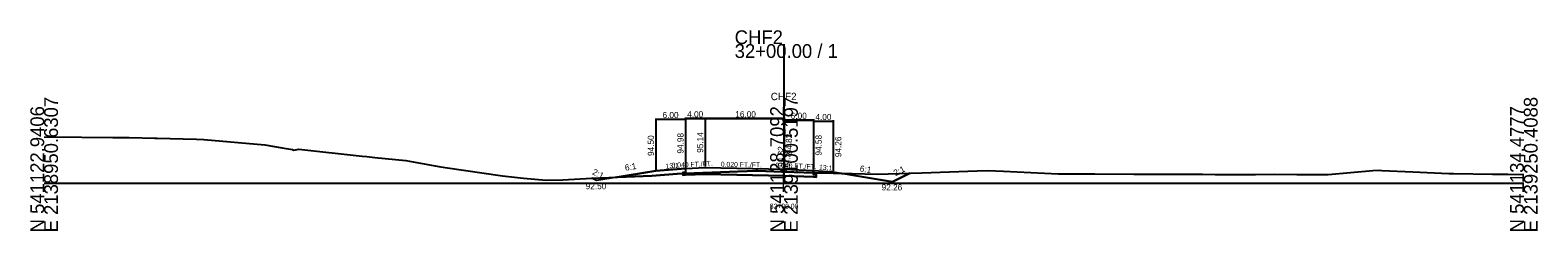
# Model space of a CAD drawing. Extents: x -12831 to 2303, y -10 to 39065.
# Drawn here: x 997.2 to 1302.8, y 3990.3 to 4031 of the extents above; entities that cross this region are included whole.
import ezdxf

# ---------------------------------------------------------------- set-up
doc = ezdxf.new("R2010")
doc.units = 0
for name, color, linetype in [('Level 5', 7, 'Continuous'), ('Level 53', 7, 'Continuous'), ('Level 54', 7, 'Continuous'), ('Level 55', 7, 'Continuous'), ('Level 7', 7, 'Continuous'), ('RD_GPK_XS_Cell', 7, 'Continuous'), ('RD_XS_EwShp', 7, 'Continuous'), ('RD_XS_ExGround', 7, 'Continuous'), ('RD_XS_Pave', 7, 'Continuous'), ('RD_XS_TX_Baseline', 7, 'Continuous'), ('RD_XS_TX_Ditch', 7, 'Continuous'), ('RD_XS_TX_Elev_EX', 7, 'Continuous'), ('RD_XS_TX_Elev_PR', 7, 'Continuous'), ('RD_XS_TX_Station', 7, 'Continuous')]:
    doc.layers.add(name, color=color, linetype=linetype)

msp = doc.modelspace()

# ---------------------------------------------------------------- linework, layer by layer
at = {"layer": 'Level 5'}
for p, q in [((1130, 4002.15), (1129.5, 4002.13)), ((1129.5, 4002.13), (1129.5, 4001.63)), ((1129.5, 4001.63), (1130, 4001.65)), ((1130, 4002.98), (1130, 4002.15)), ((1134, 4001.81), (1130, 4001.65)), ((1134, 4001.81), (1130, 4001.65)), ((1130, 4001.65), (1134, 4001.81)), ((1150, 4001.49), (1134, 4001.81)), ((1150, 4001.49), (1134, 4001.81)), ((1134, 4001.81), (1150, 4001.49)), ((1134, 4001.81), (1150, 4001.49)), ((1156, 4001.25), (1150, 4001.49)), ((1150, 4001.49), (1156, 4001.25)), ((1150, 4001.49), (1156, 4001.25)), ((1156, 4002.58), (1156, 4001.75)), ((1156, 4001.75), (1156.5, 4001.73)), ((1156.5, 4001.73), (1156.5, 4001.23)), ((1156.5, 4001.23), (1156, 4001.25))]:
    msp.add_line(p, q, dxfattribs=at)
at = {"layer": 'Level 54'}
for p, q in [((1124, 4013.13), (1124, 4002.7)), ((1130, 4012.93), (1124, 4012.93)), ((1130, 4013.29), (1130, 4003.18)), ((1130, 4013.29), (1130, 4003.18)), ((1130, 4013.29), (1130, 4003.18)), ((1130, 4013.13), (1130, 4003.18)), ((1130, 4013.09), (1134, 4013.09)), ((1130, 4013.09), (1134, 4013.09)), ((1134, 4013.09), (1130, 4013.09)), ((1134, 4013.29), (1134, 4003.34)), ((1134, 4013.29), (1134, 4003.34)), ((1134, 4013.29), (1134, 4003.34)), ((1134, 4013.29), (1134, 4003.34)), ((1134, 4013.29), (1134, 4003.34)), ((1134, 4013.29), (1134, 4003.34)), ((1134, 4013.29), (1134, 4003.34)), ((1134, 4013.09), (1150, 4013.09)), ((1134, 4013.09), (1150, 4013.09)), ((1150, 4013.09), (1134, 4013.09)), ((1150, 4013.09), (1134, 4013.09)), ((1150, 4013.29), (1150, 4003.02)), ((1150, 4013.29), (1150, 4003.02)), ((1150, 4013.29), (1150, 4003.02)), ((1150, 4013.29), (1150, 4003.02)), ((1150, 4012.97), (1150, 4003.02)), ((1150, 4012.97), (1150, 4003.02)), ((1150, 4012.97), (1150, 4003.02)), ((1150, 4012.77), (1156, 4012.77)), ((1156, 4012.77), (1150, 4012.77)), ((1156, 4012.77), (1150, 4012.77)), ((1156, 4012.97), (1156, 4002.78)), ((1156, 4012.97), (1156, 4002.78)), ((1156, 4012.97), (1156, 4002.78)), ((1156, 4012.73), (1156, 4002.78)), ((1156, 4012.53), (1160, 4012.53)), ((1160, 4012.73), (1160, 4002.46))]:
    msp.add_line(p, q, dxfattribs=at)
at = {"layer": 'Level 7'}
for p, q in [((1124, 4002.5), (1112, 4000.5)), ((1130, 4002.98), (1124, 4002.5)), ((1156, 4002.58), (1160, 4002.26)), ((1160, 4002.26), (1172, 4000.26)), ((1172, 4000.26), (1175.53, 4002.02)), ((1112, 4000.5), (1111.02, 4000.99))]:
    msp.add_line(p, q, dxfattribs=at)
at = {"layer": 'RD_GPK_XS_Cell'}
for p, q in [((1150, 4000), (1150, 4028.18)), ((1000, 4000), (1150, 4000)), ((1150, 4000), (1300, 4000))]:
    msp.add_line(p, q, dxfattribs=at)
at = {"layer": 'RD_XS_EwShp'}
for points in [[(1130, 4002.15), (1129.5, 4002.13), (1129.5, 4001.91), (1128.36, 4001.85), (1123.19, 4001.5), (1116.25, 4001.21), (1124, 4002.5), (1130, 4002.98)], [(1129.5, 4001.91), (1129.5, 4001.63), (1130, 4001.65), (1134, 4001.81), (1150, 4001.49), (1156, 4001.25), (1156.5, 4001.23), (1156.5, 4001.73), (1156, 4001.75), (1156, 4002.11), (1150, 4002.28), (1149.55, 4002.29), (1144.68, 4002.49), (1144.3, 4002.49), (1131.78, 4002.04)], [(1156, 4002.58), (1160, 4002.26), (1161.73, 4001.97), (1156.13, 4002.11), (1156, 4002.11)], [(1163.81, 4001.92), (1168.91, 4001.84), (1175.53, 4002.02), (1172, 4000.26), (1161.73, 4001.97)], [(1116.25, 4001.21), (1112, 4000.5), (1111.02, 4000.99)]]:
    msp.add_lwpolyline(points, close=True, dxfattribs=at)
at = {"layer": 'RD_XS_ExGround'}
for p, q in [((1000, 4009.33), (1001.25, 4009.39)), ((1001.25, 4009.39), (1013.89, 4009.27)), ((1013.89, 4009.27), (1017.24, 4009.24)), ((1017.24, 4009.24), (1022.46, 4009.11)), ((1022.46, 4009.11), (1022.91, 4009.11)), ((1022.91, 4009.11), (1028.17, 4009)), ((1028.17, 4009), (1030.91, 4008.94)), ((1030.91, 4008.94), (1032.4, 4008.81)), ((1032.4, 4008.81), (1044.76, 4007.74)), ((1044.76, 4007.74), (1048.27, 4007.13)), ((1048.27, 4007.13), (1050.32, 4006.78)), ((1050.32, 4006.78), (1050.62, 4006.7)), ((1050.62, 4006.7), (1051.63, 4006.91)), ((1051.63, 4006.91), (1064.49, 4005.44)), ((1064.49, 4005.44), (1065.4, 4005.38)), ((1065.4, 4005.38), (1067.07, 4005.2)), ((1067.07, 4005.2), (1073.3, 4004.58)), ((1073.3, 4004.58), (1080.01, 4003.37)), ((1080.01, 4003.37), (1081.3, 4003.15)), ((1081.3, 4003.15), (1092.95, 4001.44)), ((1092.95, 4001.44), (1097.15, 4000.98)), ((1111.03, 4000.99), (1123.19, 4001.5)), ((1123.19, 4001.5), (1128.36, 4001.85)), ((1128.36, 4001.85), (1131.78, 4002.04)), ((1131.78, 4002.04), (1144.3, 4002.49)), ((1144.3, 4002.49), (1144.68, 4002.49)), ((1144.68, 4002.49), (1149.55, 4002.29)), ((1149.55, 4002.29), (1150, 4002.28)), ((1150, 4002.28), (1156.13, 4002.11)), ((1156.13, 4002.11), (1163.81, 4001.92)), ((1163.81, 4001.92), (1168.91, 4001.84)), ((1168.91, 4001.84), (1177.96, 4002.09)), ((1177.96, 4002.09), (1189.19, 4002.47)), ((1189.19, 4002.47), (1191.24, 4002.55)), ((1191.24, 4002.55), (1194.48, 4002.41)), ((1194.48, 4002.41), (1205.61, 4001.88)), ((1205.61, 4001.88), (1206.53, 4001.9)), ((1206.53, 4001.9), (1207.26, 4001.85)), ((1207.26, 4001.85), (1213.03, 4001.86)), ((1213.03, 4001.86), (1220.92, 4001.83)), ((1220.92, 4001.83), (1232.83, 4001.81)), ((1232.83, 4001.81), (1234.84, 4001.81)), ((1234.84, 4001.81), (1237.42, 4001.73)), ((1237.42, 4001.73), (1242.11, 4001.72)), ((1242.11, 4001.72), (1245.61, 4001.75)), ((1245.61, 4001.75), (1249.35, 4001.82)), ((1249.35, 4001.82), (1254, 4001.76)), ((1254, 4001.76), (1260.3, 4001.71)), ((1260.3, 4001.71), (1269.41, 4002.57)), ((1269.41, 4002.57), (1270.69, 4002.59)), ((1270.69, 4002.59), (1271.18, 4002.58)), ((1271.18, 4002.58), (1277.52, 4002.31)), ((1277.52, 4002.31), (1284.76, 4001.97)), ((1284.76, 4001.97), (1285.76, 4001.96)), ((1285.76, 4001.96), (1293.66, 4001.79)), ((1293.66, 4001.79), (1296.74, 4001.83)), ((1296.74, 4001.83), (1300, 4001.77)), ((1097.15, 4000.98), (1101.75, 4000.58)), ((1101.75, 4000.58), (1105.17, 4000.69)), ((1105.17, 4000.69), (1111.03, 4000.99))]:
    msp.add_line(p, q, dxfattribs=at)
at = {"layer": 'RD_XS_Pave'}
for p, q in [((1130, 4002.98), (1134, 4003.14)), ((1134, 4003.14), (1150, 4002.82)), ((1150, 4002.82), (1156, 4002.58))]:
    msp.add_line(p, q, dxfattribs=at)

# ---------------------------------------------------------------- texts
at = {"layer": 'Level 53'}
for s, rotation, p in [('94.50', 90, (1123.63, 4005.5)), ('94.98', 90, (1129.63, 4005.98)), ('95.14', 90, (1133.62, 4006.14)), ('95.14', 90, (1133.62, 4006.14)), ('94.82', 90, (1151.63, 4005.82)), ('94.82', 90, (1151.63, 4005.82)), ('94.58', 90, (1157.63, 4005.58)), ('94.26', 90, (1161.63, 4005.26)), ('6:1', 9.4623, (1117.84, 4002.49)), ('6:1', 350.5377, (1165.3, 4002.39))]:
    msp.add_text(s, height=1.25, rotation=rotation, dxfattribs=at).set_placement(p)
msp.add_text('92.26', height=1.25, dxfattribs=at).set_placement((1169.79, 3998.51))
at = {"layer": 'Level 54'}
for s, p in [('6.00', (1125.37, 4013.18)), ('4.00', (1130.37, 4013.34)), ('4.00', (1130.37, 4013.34)), ('4.00', (1130.37, 4013.34)), ('16.00', (1140.12, 4013.34)), ('16.00', (1140.12, 4013.34)), ('16.00', (1140.12, 4013.34)), ('16.00', (1140.12, 4013.34)), ('6.00', (1151.37, 4013.02)), ('6.00', (1151.37, 4013.02)), ('6.00', (1151.37, 4013.02)), ('4.00', (1156.37, 4012.78))]:
    msp.add_text(s, height=1.25, dxfattribs=at).set_placement(p)
at = {"layer": 'Level 55'}
for s, height, rotation, p in [('2:1', 1.25, 333.4349, (1111.01, 4001.83)), ('13:1', 1, 4.5739, (1126.03, 4002.91)), ('0.040 FT./FT.', 1, 2.2906, (1127.22, 4003.12)), ('0.040 FT./FT.', 1, 2.2906, (1127.22, 4003.12)), ('0.040 FT./FT.', 1, 2.2906, (1127.22, 4003.12)), ('0.020 FT./FT.', 1, 358.8542, (1137.18, 4003.33)), ('0.020 FT./FT.', 1, 358.8542, (1137.18, 4003.33)), ('0.020 FT./FT.', 1, 358.8542, (1137.18, 4003.33)), ('0.020 FT./FT.', 1, 358.8542, (1137.18, 4003.33)), ('0.040 FT./FT.', 1, 357.7094, (1148.24, 4003.14)), ('0.040 FT./FT.', 1, 357.7094, (1148.24, 4003.14)), ('0.040 FT./FT.', 1, 357.7094, (1148.24, 4003.14)), ('13:1', 1, 355.4261, (1157.07, 4002.75)), ('2:1', 1.25, 26.5651, (1172.59, 4001.39))]:
    msp.add_text(s, height=height, rotation=rotation, dxfattribs=at).set_placement(p)
at = {"layer": 'RD_GPK_XS_Cell'}
for s, p in [('CHF2', (1140, 4028.18)), ('32+00.00 / 1', (1140, 4025.38))]:
    msp.add_text(s, height=2.8, dxfattribs=at).set_placement(p)
for s, p in [('E 2138950.6307', (1002.8, 3990)), ('E 2139100.5197', (1152.8, 3990)), ('E 2139250.4088', (1302.8, 3990)), ('N 541122.9406', (1000, 3990)), ('N 541128.7092', (1150, 3990)), ('N 541134.4777', (1300, 3990))]:
    msp.add_text(s, height=2.8, rotation=90, dxfattribs=at).set_placement(p)
at = {"layer": 'RD_XS_TX_Baseline'}
msp.add_text('CHF2', height=1.5, dxfattribs=at).set_placement((1147.31, 4016.82))
at = {"layer": 'RD_XS_TX_Ditch'}
msp.add_text('92.50', height=1.25, dxfattribs=at).set_placement((1109.79, 3998.75))
at = {"layer": 'RD_XS_TX_Elev_EX'}
msp.add_text('94.28', height=1, rotation=90, dxfattribs=at).set_placement((1151.25, 4003.28))
at = {"layer": 'RD_XS_TX_Elev_PR'}
msp.add_text(' 94.82', height=1.25, rotation=90, dxfattribs=at).set_placement((1150, 4002.82))
at = {"layer": 'RD_XS_TX_Station'}
msp.add_text('32+00.00', height=1, dxfattribs=at).set_placement((1147.12, 3994.82))

doc.saveas('drawing.dxf')
